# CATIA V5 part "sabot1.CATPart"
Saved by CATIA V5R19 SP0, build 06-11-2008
Part number: sabot1
Bounding box of the stored display mesh (mm): x 90.052 to 312.443, y 208.914 to 579.939, z -30 to 30
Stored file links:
  C:\Users\Thibaud\Desktop\IFMA\thinkmotion\IAO\modele_catia\sabot1.CATPart
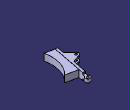
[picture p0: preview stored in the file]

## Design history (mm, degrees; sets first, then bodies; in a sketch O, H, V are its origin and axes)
Body1 (main body)
  Plane1: stored without definition
  DatumPoint1
  Line1: stored without definition
  Line2 "axe_pivot_sabot1_batit": stored without definition
  Plane2: stored without definition
  Sketch1 on Plane1, origin (0, 0, 0), H (1, 0, 0), V (0, 1, 0)
    point P1 (207.4461, 520.7197)
    line L1 (207.4461, 520.7197) -> (217.2662, 518.8313)
    line L2 (217.2662, 518.8313) -> (160.612, 224.2293)
    line L3 (160.612, 224.2293) -> (150.7919, 226.1178)
    point P2 (217.2662, 518.8313)
    point P3 (160.612, 224.2293)
    point P4 (150.7919, 226.1178)
    axis line L4 (207.4461, 520.7197) -> (150.7919, 226.1178)
    reference projected point E1 (215, 560) from vertex of DatumPoint1
    reference projected line E2 (110, 355) -> (240, 330) from Line1
    reference projected point E3 (215, 560) from Line2
    point P5 (150.7919, 226.1178)
    point P6 (140.9718, 228.0063)
    line L5 (140.9718, 228.0063) -> (150.7919, 226.1178)
    point P7 (197.626, 522.6082)
    line L6 (197.626, 522.6082) -> (140.9718, 228.0063)
    point P8 (207.4461, 520.7197)
    line L7 (207.4461, 520.7197) -> (197.626, 522.6082)
    length L3 = 10
    distance E3 L1 = 40
    length L2 = 300
    coincidence: L4 E1, P1 P8, P4 P5
    perpendicularity: L4 E2, L1 L4, L3 L4, L2 L3, L1 L2
    symmetry: P4 P5 L4, P3 P6 L4, L3 L5 L4, P2 P7 L4, L2 L6 L4, P1 P8 L4, L1 L7 L4
  Pad1: profile Sketch1, direction (0, 0, 1), length 30, mirrored extent
  Line3 "axe_pivot_sabot1_roue1": stored without definition
  Plane3: stored without definition
  Sketch2 on Plane2, origin (0, 0, 0), H (1, 0, 0), V (0, 1, 0)
    line L1 (209.7123, 479.551) -> (312.4426, 459.7952)
    line L2 (240.2531, 208.9137) -> (160.612, 224.2293)
    line L3 (160.612, 224.2293) -> (209.7123, 479.551)
    reference projected line E1 (160.612, 224.2293) -> (217.2662, 518.8313) from edge [face of Pad1 from Sketch1.L2 | end face of Pad1]
    reference projected line E2 (150.7919, 226.1178) -> (160.612, 224.2293) from edge [face of Pad1 from Sketch1.L3 | end face of Pad1]
    arc A1 centre (500, 270) radius 266.8333 from (312.4426, 459.7952) to (240.2531, 208.9137) ccw
    point P3 (500, 270)
    reference projected point E3 (240, 330) from Line3
    point P4 (312.4426, 459.7952)
    point P5 (312.4426, 459.7952)
    point P6 (240.2531, 208.9137)
    point P7 (240.2531, 208.9137)
    distance P3 H = 270
    distance P3 V = 500
    length L3 = 260
    coincidence: E1 L3, L2 E2, E3 A1, P4 L1, P5 A1, P6 L2, P7 A1, P4 P5, P6 P7
    perpendicularity: L1 L3, L3 L2
  Pad2: profile Sketch2, direction (0, 0, 1), length 29, mirrored extent
  Line4 "axe_pivot_sabot1_batit": stored without definition
  Sketch3 on Plane3, origin (0, 0, 0), H (1, 0, 0), V (0, 1, 0)
    circle A1 centre (215, 560) radius 10
    point P1 (215, 560)
    reference projected point E1 (215, 560) from Line4
    arc A2 centre (215, 560) radius 20 from (225.2782, 542.8431) to (199.0914, 547.8791) ccw
    line L1 (220.5973, 536.1532) -> (217.2662, 518.8313)
    point P2 (221.5491, 541.1027)
    line L2 (200.9572, 539.9301) -> (197.626, 522.6082)
    point P4 (201.909, 544.8796)
    reference projected line E2 (160.612, 224.2293) -> (217.2662, 518.8313) from edge [face of Pad1 from Sketch1.L2 | end face of Pad1]
    reference projected line E3 (197.626, 522.6082) -> (140.9718, 228.0063) from edge [face of Pad1 from Sketch1.L6 | end face of Pad1]
    line L3 (197.626, 522.6082) -> (217.2662, 518.8313)
    reference projected line E4 (217.2662, 518.8313) -> (207.4461, 520.7197) from edge [face of Pad1 from Sketch1.L1 | end face of Pad1]
    point P6 (201.909, 544.8796)
    point P7 (221.5491, 541.1027)
    arc A3 centre (230.4174, 534.2647) radius 10 from (225.2782, 542.8431) to (220.5973, 536.1532) ccw
    arc A4 centre (191.1371, 541.8186) radius 10 from (199.0914, 547.8791) to (200.9572, 539.9301) cw
    radius A1 = 10
    radius A2 = 20
    radius A3 = 10
    radius A4 = 10
    coincidence: P1 E1, P2 A2, P4 A2, L1 E2, L2 E3, L3 E4, P6 L2, P7 L1, A2 P7, L1 P2, A2 P6, L2 P4
    parallelism: L2 L1
    tangency: A3 A2, A3 L1, A4 A2, A4 L2
  Pad3: profile Sketch3, direction (0, 0, 1), length 15, mirrored extent
  Line5 "axe_pivot_sabot1_bielette3": stored without definition
  Line6: stored without definition
  Line7: stored without definition
  Sketch4 on end face of Pad1, origin (0, 0, 30), H (1, 0, 0), V (0, 1, 0)
    circle A1 centre (110, 355) radius 10
    point P1 (110, 355)
    reference projected point E1 (110, 355) from Line5
    arc A2 centre (110, 355) radius 20 from (103.4509, 373.8973) to (96.909, 339.8796) ccw
    line L1 (103.4509, 373.8973) -> (162.8, 394.4656)
    point P2 (103.4509, 373.8973)
    point P3 (173.7104, 398.2467)
    line L2 (96.909, 339.8796) -> (144.3962, 298.7659)
    point P4 (96.909, 339.8796)
    point P5 (153.126, 291.2078)
    reference projected line E2 (197.626, 522.6082) -> (140.9718, 228.0063) from edge [face of Pad1 from Sketch1.L6 | end face of Pad1]
    reference projected line E3 (197.626, 522.6082) -> (140.9718, 228.0063) from edge [face of Pad1 from Sketch1.L6 | end face of Pad1]
    point P6 (103.4509, 373.8973)
    point P7 (96.909, 339.8796)
    arc A3 centre (156.2509, 413.3629) radius 20 from (175.891, 409.586) to (162.8, 394.4656) cw
    arc A4 centre (131.3052, 283.6455) radius 20 from (144.3962, 298.7659) to (150.9453, 279.8686) cw
    line L3 (150.9453, 279.8686) -> (175.891, 409.586)
    reference projected line E4 (110, 355) -> (240, 330) from Line6
    reference projected line E5 (110, 355) -> (240, 330) from Line7
    reference projected line E6 (197.626, 522.6082) -> (140.9718, 228.0063) from edge [face of Pad1 from Sketch1.L6 | end face of Pad1]
    radius A1 = 10
    radius A2 = 20
    radius A3 = 20
    radius A4 = 20 {= Sketch4.radius(A3)}
    angle L1 E4 = 30
    angle E5 L2 = 30 {= Sketch4.angle(L1 E4)}
    coincidence: E1 P1, P2 A2, P4 A2, E2 P3, P5 E3, P6 L1, P7 L2, L1 P3, L2 P5, L3 E6, P2 P6, P4 P7
    tangency: L1 A2, L2 A2, A3 L1, A4 L2, L3 A3, L3 A4
  Pad4: profile Sketch4, direction (0, 0, -1), length 15
  Line8 "axe_pivot_sabot1_bielette3": stored without definition
  RectPattern1: of Pad4, direction 1 instances 2, spacing 45, along Line8 reversed
  Plane4: stored without definition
